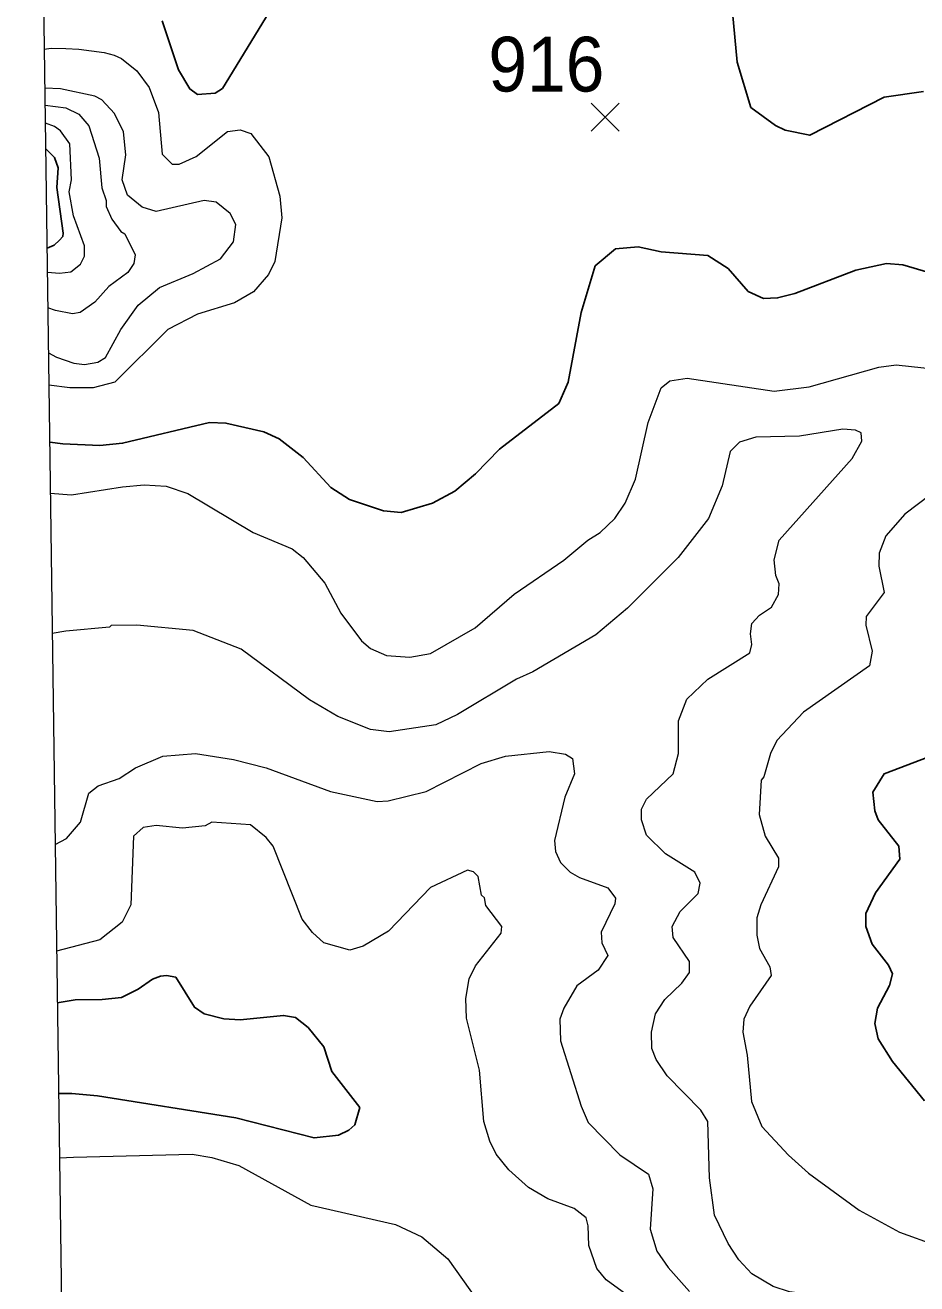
# Model space of a CAD drawing. Extents: x 265 to 291.4, y 7731.5 to 7759.6.
# Drawn here: x 265.126 to 266.429, y 7742.944 to 7744.783 of the extents above; entities that cross this region are included whole.
import ezdxf
from ezdxf.enums import TextEntityAlignment as Align

# ---------------------------------------------------------------- set-up
doc = ezdxf.new("R2010")
doc.units = 0
doc.header["$LTSCALE"] = 0.032
for name, color, linetype, lineweight in [('1', 7, 'Continuous', 25), ('2', 7, 'Continuous', 13), ('21', 7, 'Continuous', 25), ('61', 7, 'Continuous', 13), ('63', 7, 'Continuous', 25)]:
    doc.layers.add(name, color=color, linetype=linetype, lineweight=lineweight)

msp = doc.modelspace()

# ---------------------------------------------------------------- linework, layer by layer
at = {"layer": '1'}
for points in [[(265.326, 7744.7897), (265.3499, 7744.7181), (265.3666, 7744.6903), (265.3778, 7744.6823), (265.4032, 7744.6839), (265.4143, 7744.691), (265.4931, 7744.8199)], [(266.1597, 7744.8024), (266.1669, 7744.7292), (266.1867, 7744.6632), (266.2226, 7744.6369), (266.2369, 7744.6298), (266.2727, 7744.6226), (266.3816, 7744.6783), (266.4389, 7744.6863)], [(265.1576, 7744.4575), (265.1682, 7744.4617), (265.1757, 7744.469), (265.1808, 7744.4748), (265.1813, 7744.4793), (265.1717, 7744.5463), (265.1741, 7744.5749), (265.1685, 7744.59), (265.1556, 7744.6029)], [(265.9887, 7744.4564), (265.9592, 7744.4317), (265.9385, 7744.3633), (265.9195, 7744.2615), (265.9059, 7744.2305), (265.8192, 7744.1636), (265.7842, 7744.1278), (265.754, 7744.1024), (265.7214, 7744.0849), (265.6753, 7744.0713), (265.6498, 7744.0737), (265.5997, 7744.0904), (265.5726, 7744.1079), (265.5321, 7744.1517), (265.4971, 7744.1787), (265.4748, 7744.1891), (265.4191, 7744.2018), (265.3953, 7744.2026), (265.268, 7744.1724), (265.2346, 7744.1692), (265.1809, 7744.1716), (265.1615, 7744.174)], [(266.205, 7744.384), (266.1828, 7744.3943), (266.1533, 7744.4277), (266.1239, 7744.4468), (266.0555, 7744.4524), (266.0221, 7744.4595), (265.9887, 7744.4564)], [(266.4469, 7744.4221), (266.4087, 7744.4333), (266.3848, 7744.4349), (266.3403, 7744.4253), (266.2512, 7744.3911), (266.2257, 7744.3848), (266.205, 7744.384)], [(266.4405, 7743.2114), (266.3936, 7743.2687), (266.3729, 7743.3021), (266.3681, 7743.3244), (266.3721, 7743.3467), (266.3896, 7743.3801), (266.3936, 7743.3968), (266.388, 7743.4095), (266.3641, 7743.4405), (266.3546, 7743.466), (266.3546, 7743.4851), (266.3689, 7743.5153), (266.4047, 7743.5646), (266.4031, 7743.5837), (266.3729, 7743.6219), (266.3681, 7743.6354), (266.3649, 7743.6625), (266.3816, 7743.6895), (266.4469, 7743.7142)], [(265.1726, 7743.3548), (265.1989, 7743.3589), (265.2384, 7743.3593), (265.2664, 7743.3626), (265.2906, 7743.3748), (265.312, 7743.3891), (265.3233, 7743.3936), (265.3322, 7743.3948), (265.3459, 7743.392), (265.373, 7743.3483), (265.3873, 7743.3387), (265.4159, 7743.3315), (265.4398, 7743.3299), (265.5034, 7743.3363), (265.5209, 7743.3331), (265.5392, 7743.3188), (265.5623, 7743.2902), (265.5742, 7743.2544), (265.6148, 7743.2019), (265.6076, 7743.1764), (265.5989, 7743.1685), (265.5838, 7743.1613), (265.548, 7743.1573), (265.4334, 7743.1868), (265.2314, 7743.2186), (265.1938, 7743.222), (265.1744, 7743.2221)]]:
    msp.add_lwpolyline(points, dxfattribs=at)
at = {"layer": '2'}
for points in [[(265.1536, 7744.7485), (265.1636, 7744.7498), (265.185, 7744.7493), (265.2043, 7744.7483), (265.2409, 7744.7435), (265.2556, 7744.7396), (265.2664, 7744.7348), (265.2887, 7744.7165), (265.3069, 7744.6926), (265.3205, 7744.656), (265.326, 7744.5948), (265.3404, 7744.5805), (265.3507, 7744.5805), (265.3754, 7744.5916), (265.4215, 7744.6282), (265.4398, 7744.6306), (265.4557, 7744.625), (265.4819, 7744.5908), (265.4979, 7744.5335), (265.501, 7744.5017), (265.4907, 7744.4381), (265.4812, 7744.419), (265.4597, 7744.3935), (265.4318, 7744.3776), (265.3778, 7744.3609), (265.334, 7744.3386), (265.2568, 7744.2615), (265.225, 7744.2535), (265.1908, 7744.2535), (265.1604, 7744.2573)], [(265.1597, 7744.3044), (265.1716, 7744.2983), (265.1969, 7744.2893), (265.2124, 7744.2877), (265.2317, 7744.291), (265.2431, 7744.2979), (265.2656, 7744.3386), (265.291, 7744.3744), (265.3221, 7744.3999), (265.3714, 7744.4206), (265.4112, 7744.4421), (265.4302, 7744.4667), (265.4334, 7744.4922), (265.4255, 7744.5081), (265.4048, 7744.5248), (265.3873, 7744.5272), (265.3173, 7744.5113), (265.2968, 7744.5175), (265.2753, 7744.5348), (265.2672, 7744.5574), (265.2727, 7744.594), (265.2696, 7744.6274), (265.256, 7744.6545), (265.2377, 7744.6743), (265.2274, 7744.6799), (265.1773, 7744.6902), (265.1544, 7744.6913)], [(265.1548, 7744.6663), (265.1852, 7744.6624), (265.2043, 7744.6536), (265.2186, 7744.6362), (265.2338, 7744.5892), (265.2377, 7744.5455), (265.2441, 7744.5272), (265.2441, 7744.5184), (265.2521, 7744.5001), (265.2656, 7744.4818), (265.2712, 7744.4787), (265.2863, 7744.4476), (265.2847, 7744.4349), (265.2759, 7744.4222), (265.2481, 7744.4015), (265.2274, 7744.3784), (265.2059, 7744.3633), (265.1948, 7744.3617), (265.1701, 7744.3665), (265.1588, 7744.3702)], [(265.1581, 7744.4225), (265.1757, 7744.4209), (265.1924, 7744.423), (265.2067, 7744.4341), (265.2123, 7744.446), (265.2123, 7744.4612), (265.1964, 7744.5049), (265.19, 7744.5399), (265.1932, 7744.5574), (265.1908, 7744.6099), (265.1773, 7744.629), (265.1685, 7744.6354), (265.1551, 7744.6403)], [(265.1624, 7744.0996), (265.1935, 7744.097), (265.268, 7744.1087), (265.2998, 7744.1119), (265.3316, 7744.1095), (265.3634, 7744.0992), (265.4589, 7744.0419), (265.5162, 7744.0181), (265.5321, 7744.0053), (265.5639, 7743.968), (265.587, 7743.9242), (265.6172, 7743.8836), (265.6307, 7743.8725), (265.6538, 7743.8622), (265.688, 7743.8598), (265.7182, 7743.8653), (265.7835, 7743.9027), (265.8407, 7743.952), (265.9131, 7744.0014), (265.9481, 7744.0308), (265.9664, 7744.0419), (265.9879, 7744.0626), (266.003, 7744.0849), (266.0181, 7744.1199), (266.0364, 7744.2026), (266.0555, 7744.2535), (266.0682, 7744.2639), (266.0937, 7744.2678), (266.221, 7744.2487), (266.2719, 7744.2551), (266.3737, 7744.2838), (266.3992, 7744.2869), (266.4755, 7744.279)], [(266.1533, 7743.003), (266.1335, 7743.0444), (266.1263, 7743.0989), (266.1236, 7743.181), (266.1137, 7743.1976), (266.0642, 7743.248), (266.0483, 7743.2719), (266.042, 7743.2878), (266.0412, 7743.3117), (266.0475, 7743.3387), (266.0611, 7743.3594), (266.0857, 7743.3833), (266.0969, 7743.3992), (266.0969, 7743.4151), (266.073, 7743.4501), (266.0714, 7743.466), (266.0833, 7743.4883), (266.1096, 7743.5145), (266.1128, 7743.5296), (266.1048, 7743.5456), (266.0619, 7743.5726), (266.034, 7743.5996), (266.0269, 7743.6219), (266.0269, 7743.6378), (266.034, 7743.6521), (266.073, 7743.6895), (266.081, 7743.719), (266.081, 7743.7667), (266.0929, 7743.7985), (266.1239, 7743.8279), (266.1852, 7743.8661), (266.1883, 7743.8781), (266.186, 7743.894), (266.1883, 7743.9091), (266.1995, 7743.921), (266.217, 7743.9329), (266.2273, 7743.9512), (266.2281, 7743.9672), (266.2233, 7743.9791), (266.221, 7744.0022), (266.2281, 7744.0308), (266.3347, 7744.1501), (266.349, 7744.1756), (266.3482, 7744.1875), (266.3395, 7744.1915), (266.3212, 7744.1931), (266.2576, 7744.1827), (266.1939, 7744.1811), (266.1701, 7744.174), (266.1565, 7744.1605), (266.1446, 7744.1103), (266.1247, 7744.0626), (266.0802, 7744.0053), (266.0062, 7743.9313), (265.96, 7743.8924), (265.8678, 7743.8383), (265.8439, 7743.8279), (265.758, 7743.7762), (265.7262, 7743.7611), (265.6578, 7743.7508), (265.6307, 7743.754), (265.583, 7743.7731), (265.5416, 7743.7977), (265.4414, 7743.8717), (265.3714, 7743.8987), (265.2887, 7743.9067), (265.2513, 7743.9059), (265.2489, 7743.9035), (265.1852, 7743.8979), (265.1653, 7743.8943)], [(266.4501, 7744.0976), (266.4119, 7744.069), (266.384, 7744.0372), (266.3745, 7744.0117), (266.3737, 7743.9926), (266.3816, 7743.9544), (266.3554, 7743.9194), (266.3546, 7743.9067), (266.3641, 7743.8685), (266.3602, 7743.847), (266.2639, 7743.7794), (266.2249, 7743.7381), (266.2154, 7743.719), (266.2058, 7743.6847), (266.2019, 7743.68), (266.1987, 7743.6299), (266.2074, 7743.5981), (266.2273, 7743.5662), (266.2273, 7743.5535), (266.2011, 7743.4978), (266.1955, 7743.4787), (266.1955, 7743.4533), (266.1995, 7743.4342), (266.2146, 7743.4071), (266.2162, 7743.3944), (266.1852, 7743.3499), (266.1764, 7743.3308), (266.1748, 7743.3117), (266.1812, 7743.2783), (266.1875, 7743.2106), (266.2027, 7743.1741), (266.2416, 7743.1319), (266.2711, 7743.1056), (266.3451, 7743.0515), (266.4039, 7743.0197), (266.458, 7742.9998)], [(265.1695, 7743.5858), (265.186, 7743.5948), (265.2067, 7743.6187), (265.2186, 7743.6609), (265.2322, 7743.672), (265.2632, 7743.6824), (265.2871, 7743.6983), (265.3268, 7743.715), (265.3746, 7743.719), (265.4303, 7743.7102), (265.478, 7743.6983), (265.5719, 7743.6633), (265.6403, 7743.6489), (265.6562, 7743.6497), (265.7119, 7743.6633), (265.7922, 7743.7046), (265.828, 7743.715), (265.8916, 7743.7221), (265.9155, 7743.7182), (265.9258, 7743.7118), (265.929, 7743.6895), (265.9147, 7743.6553), (265.8996, 7743.5917), (265.9012, 7743.5758), (265.9083, 7743.5599), (265.9227, 7743.5455), (265.9362, 7743.5376), (265.9775, 7743.5225), (265.9887, 7743.5074), (265.9879, 7743.4994), (265.968, 7743.458), (265.9688, 7743.4421), (265.9775, 7743.4238), (265.9632, 7743.4024), (265.9322, 7743.3793), (265.9131, 7743.3467), (265.9075, 7743.3308), (265.9083, 7743.299), (265.9386, 7743.2035), (265.9489, 7743.1796), (265.995, 7743.1327), (266.0372, 7743.1041), (266.0436, 7743.0826), (266.0396, 7743.0237), (266.0491, 7742.9919), (266.0658, 7742.968), (266.0969, 7742.933)], [(266.0038, 7742.929), (265.9751, 7742.9497), (265.9616, 7742.9664), (265.9497, 7742.9999), (265.9489, 7743.0285), (265.9457, 7743.0404), (265.9282, 7743.0539), (265.89, 7743.0683), (265.8614, 7743.085), (265.8328, 7743.1104), (265.8145, 7743.1335), (265.8049, 7743.1526), (265.7962, 7743.1812), (265.7898, 7743.256), (265.7707, 7743.3324), (265.7699, 7743.361), (265.7747, 7743.3896), (265.7842, 7743.4087), (265.8216, 7743.4565), (265.8224, 7743.466), (265.7994, 7743.497), (265.797, 7743.5082), (265.793, 7743.5121), (265.7882, 7743.5392), (265.7811, 7743.5463), (265.7723, 7743.5487), (265.7182, 7743.5233), (265.657, 7743.4596), (265.6196, 7743.4374), (265.6005, 7743.4318), (265.5623, 7743.4421), (265.5456, 7743.4572), (265.5305, 7743.4771), (265.4883, 7743.5837), (265.478, 7743.5964), (265.4549, 7743.6148), (265.3984, 7743.6187), (265.3889, 7743.6132), (265.3555, 7743.61), (265.3173, 7743.6139), (265.2982, 7743.6108), (265.2839, 7743.5981), (265.2799, 7743.4978), (265.2672, 7743.4724), (265.2346, 7743.4469), (265.1716, 7743.43)], [(265.1757, 7743.128), (265.1963, 7743.1291), (265.3698, 7743.1335), (265.3984, 7743.1287), (265.4382, 7743.1168), (265.5432, 7743.0587), (265.6673, 7743.0309), (265.7055, 7743.0126), (265.7437, 7742.9807), (265.8296, 7742.8598)], [(266.4167, 7742.9012), (266.3212, 7742.9219), (266.2432, 7742.9322), (266.2194, 7742.9402), (266.1883, 7742.9585), (266.1692, 7742.9792), (266.1533, 7743.003)]]:
    msp.add_lwpolyline(points, dxfattribs=at)
at = {"layer": '21'}
for p, q in [((265.9531, 7744.6697), (265.9943, 7744.6285)), ((265.9943, 7744.6697), (265.9531, 7744.6285))]:
    msp.add_line(p, q, dxfattribs=at)
at = {"layer": '63', "lineweight": 13}
msp.add_lwpolyline([(265.1256, 7746.7981), (265.1333, 7746.2332), (265.141, 7745.6682), (265.1487, 7745.1033), (265.1565, 7744.5383), (265.1642, 7743.9734), (265.1719, 7743.4084), (265.1797, 7742.8434), (265.1874, 7742.2785), (265.1952, 7741.7135), (265.2029, 7741.1486), (265.2106, 7740.5836), (265.2184, 7740.0186), (265.2261, 7739.4537), (265.2339, 7738.8887), (265.2416, 7738.3238), (265.2494, 7737.7588)], dxfattribs=at)

# ---------------------------------------------------------------- texts
at = {"layer": '61', "width": 0.95}
msp.add_text('916', height=0.08, dxfattribs=at).set_placement((265.8877, 7744.6865), align=Align.CENTER)

doc.saveas('drawing.dxf')
